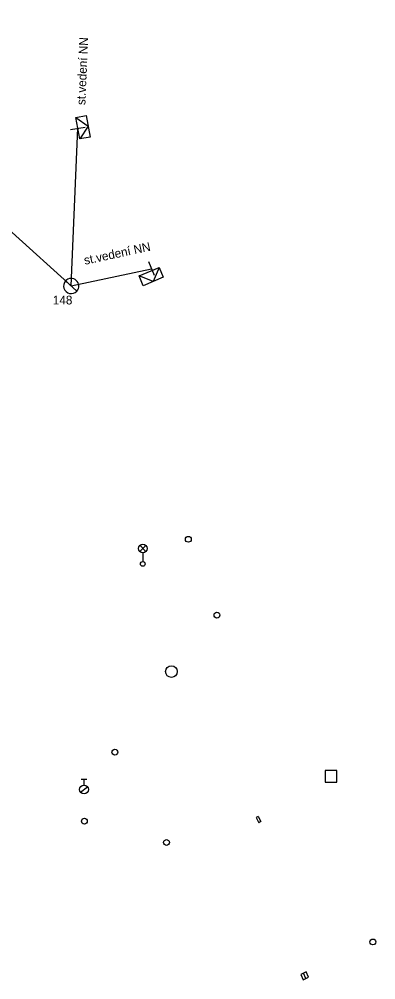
# Model space of a CAD drawing. Extents: x -584388 to -581645, y -1210859 to -1208922.
# Drawn here: x -583224.9 to -583194.4, y -1209690.5 to -1209608.3 of the extents above; entities that cross this region are included whole.
import ezdxf

# ---------------------------------------------------------------- set-up
doc = ezdxf.new("R2010")
doc.units = 0
for name, color, linetype in [('CIZÍ_NADZEM', 7, 'Continuous'), ('ELE_EON', 7, 'Continuous'), ('ELE_EON_POPIS', 7, 'Continuous')]:
    doc.layers.add(name, color=color, linetype=linetype)

msp = doc.modelspace()

# ---------------------------------------------------------------- linework, layer by layer
at = {"layer": 'CIZÍ_NADZEM'}
for p, q in [((-583214.614, -1209653.858), (-583214.086, -1209653.33)), ((-583214.078, -1209653.855), (-583214.606, -1209653.326)), ((-583214.35, -1209653.97), (-583214.35, -1209654.72)), ((-583197.74, -1209672.59), (-583198.74, -1209672.59)), ((-583198.74, -1209672.59), (-583198.74, -1209673.59)), ((-583197.74, -1209673.59), (-583197.74, -1209672.59)), ((-583219.63, -1209673.325), (-583219.13, -1209673.325)), ((-583219.38, -1209673.825), (-583219.38, -1209673.325)), ((-583198.74, -1209673.59), (-583197.74, -1209673.59)), ((-583219.674, -1209674.431), (-583219.084, -1209673.968)), ((-583200.381, -1209690.365), (-583200.599, -1209689.915))]:
    msp.add_line(p, q, dxfattribs=at)
for points in [[(-583204.47, -1209676.51), (-583204.64, -1209676.6), (-583204.42, -1209677.04)], [(-583204.47, -1209676.51), (-583204.24, -1209676.95), (-583204.42, -1209677.04)]]:
    msp.add_lwpolyline(points, dxfattribs=at)
msp.add_lwpolyline([(-583200.155, -1209690.256), (-583200.373, -1209689.805), (-583200.825, -1209690.024), (-583200.607, -1209690.474)], close=True, dxfattribs=at)
for centre, radius in [((-583210.45, -1209652.81), 0.25), ((-583214.35, -1209653.595), 0.375), ((-583214.35, -1209654.92), 0.2), ((-583208, -1209659.29), 0.25), ((-583211.9, -1209664.12), 0.5), ((-583216.74, -1209671.01), 0.25), ((-583219.38, -1209674.2), 0.375), ((-583219.35, -1209676.91), 0.25), ((-583212.32, -1209678.73), 0.25), ((-583194.65, -1209687.24), 0.25)]:
    msp.add_circle(centre, radius, dxfattribs=at)
at = {"layer": 'ELE_EON'}
for p, q in [((-583220.526, -1209617.763), (-583219.294, -1209617.557)), ((-583213.337, -1209630.241), (-583213.843, -1209629.099)), ((-583219.997, -1209631.585), (-583220.963, -1209630.715))]:
    msp.add_line(p, q, dxfattribs=at)
for points in [[(-583245.77, -1209608.34), (-583220.48, -1209631.15)], [(-583220.078, -1209616.738), (-583219.025, -1209617.499), (-583219.742, -1209618.582)], [(-583220.48, -1209631.15), (-583219.91, -1209617.66)], [(-583212.946, -1209629.565), (-583213.46, -1209630.759), (-583214.674, -1209630.295)], [(-583220.48, -1209631.15), (-583213.59, -1209629.67)]]:
    msp.add_lwpolyline(points, dxfattribs=at)
for points in [[(-583219.192, -1209616.577), (-583218.857, -1209618.421), (-583219.742, -1209618.582), (-583220.078, -1209616.738)], [(-583212.596, -1209630.395), (-583214.324, -1209631.124), (-583214.674, -1209630.295), (-583212.946, -1209629.565)]]:
    msp.add_lwpolyline(points, close=True, dxfattribs=at)
for start, end in [(137.95153, 317.95153), (317.95153, 137.95153)]:
    msp.add_arc((-583220.48, -1209631.15), 0.65, start, end, dxfattribs=at)

# ---------------------------------------------------------------- texts
at = {"layer": 'ELE_EON_POPIS'}
for rotation, p in [(87.5805, (-583219.27, -1209615.69)), (12.12316, (-583219.3, -1209629.34))]:
    msp.add_text('st.vedení NN', height=0.75, rotation=rotation, dxfattribs=at).set_placement(p)
msp.add_text('148', height=0.75, dxfattribs=at).set_placement((-583222.05, -1209632.73))

doc.saveas('drawing.dxf')
